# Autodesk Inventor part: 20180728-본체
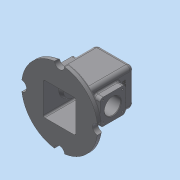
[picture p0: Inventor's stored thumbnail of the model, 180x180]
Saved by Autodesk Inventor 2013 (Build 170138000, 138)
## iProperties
Created: 2018-07
Part Number: 20180728-본체
Material: 일반
Document SubType Name: Modeling
Designer: dgall
Density: 1 g/cm^3
Author: dgall
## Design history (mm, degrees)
sketch "스케치1"
  geometry: A1 r 10 centre (0, -75) between (9.978, -74.333) and (-9.978, -74.333); A2 r 10 centre (-75, 0) between (-74.333, -9.978) and (-74.333, 9.978); A3 r 10 centre (0, 75) between (-9.978, 74.333) and (9.978, 74.333); A4 r 10 centre (75, 0) between (74.333, 9.978) and (74.333, -9.978); A5 r 75 centre (0, 0) between (-74.333, -9.978) and (-9.978, -74.333); A6 r 75 centre (0, 0) between (-9.978, 74.333) and (-74.333, 9.978); A7 r 75 centre (0, 0) between (9.978, -74.333) and (74.333, -9.978); A8 r 75 centre (0, 0) between (74.333, 9.978) and (9.978, 74.333); 1 further point
  constraints: 16 point on circle, 8 centre point, 6 equal radius, 2 horizontal alignment, 2 vertical alignment, 1 coincident
  dimensions: "d2" = 20 diameter of A1; "d3" = 75 radius of A7; "d4" = 75 distance of point (0, 0) A1.centre; "d5" = 150 distance of A2.centre A4.centre; "d6" = 75 distance of point (0, 0) A4.centre; "d7" = 75 distance of A3.centre point (0, 0)
extrude "돌출1" new body sketch "스케치1" distance "d8" = 10; taper "d9" = 0 deg
sketch "스케치2"
  geometry: L1 (-9.978, 0)-(-74.333, 0) reference; L2 (-9.978, 0)-(-9.978, -10) reference; L3 (-74.333, -10)-(-9.978, -10) reference; L4 (-74.333, 0)-(-74.333, -10) reference; L5 (9.978, 0)-(-9.978, 0) reference; L6 (9.978, 0)-(9.978, -10) reference; L7 (-9.978, -10)-(9.978, -10) reference; L8 (-9.978, 0)-(-9.978, -10) reference; L9 (74.333, 0)-(9.978, 0) reference; L10 (74.333, 0)-(74.333, -10) reference; L11 (9.978, -10)-(74.333, -10) reference; L12 (9.978, 0)-(9.978, -10) reference; L13 (-37, 0)-(-37, 100); L14 (-37, 100)-(37, 100); L15 (37, 100)-(37, 0); L16 (32, -10)-(32, 95); L17 (32, 95)-(-32, 95); L18 (-32, 95)-(-32, -10); L19 (-32, -10)-(32, -10); L20 (-37, 0)-(37, 0); 4 further points
  constraints: 16 end point, 4 midpoint, 4 perpendicular, 2 parallel, 2 point on line, 1 collinear, 1 vertical alignment
  dimensions: "d10" = 74 distance of L13.end L14.end; "d12" = 110 distance between parallel lines of L11 L14; "d13" = 5 distance between parallel lines of L14 L17; "d14" = 5 distance between parallel lines of L15 L16; "d15" = 5 distance between parallel lines of L13 L18
  node "투영된 루프1"
  node "투영된 루프2"
  node "투영된 루프3"
extrude "돌출2" join sketch "스케치2" stored distance "d16" = 74; taper "d17" = 0 deg
extrude "돌출3" cut sketch "스케치2" stored distance "d18" = 64; taper "d19" = 0 deg
sketch "스케치3"
  geometry: L1 (17, 57)-(57, 57); L2 (57, 57)-(57, 17); L3 (57, 17)-(17, 17); L4 (17, 17)-(17, 57); L5 (19.5, 54.5)-(54.5, 54.5); L6 (54.5, 54.5)-(54.5, 19.5); L7 (54.5, 19.5)-(19.5, 19.5); L8 (19.5, 19.5)-(19.5, 54.5); 5 further points
  constraints: 16 end point, 4 midpoint, 4 parallel, 4 perpendicular, 2 horizontal, 2 horizontal alignment, 2 vertical alignment
  dimensions: "d20" = 40 distance of L1.start L1.end; "d22" = 35 distance of L5.start L5.end
extrude "돌출4" join sketch "스케치3" distance "d23" = 7; taper "d24" = 0 deg
extrude "돌출5" join sketch "스케치3" distance "d25" = 10; taper "d26" = 0 deg
hole "구멍1" diameter "d29" = 21; stored, may be unused: countersink angle "d33" = 90 deg, drill point angle "d35" = 118 deg; dims "d27" = 17.5, "d28" = 17.5, "d30" = 6, "d31" = 28, "d32" = 4, "d34" = 8
sketch "스케치5"
  geometry: L1 (-74, 100)-(0, 100) reference; L2 (-62, 70)-(-12, 70); L3 (-12, 70)-(-12, 20); L4 (-12, 20)-(-62, 20); L5 (-62, 20)-(-62, 70); L6 (-62, 45)-(-12, 45); L7 (-27.022, -10)-(37.333, -10) reference; 3 further points
  constraints: 10 end point, 4 midpoint, 2 parallel, 2 perpendicular, 1 horizontal, 1 vertical alignment
  dimensions: "d37" = 50 distance of L2.start L2.end; "d39" = 55 distance between parallel lines of L7 L6
extrude "돌출6" join sketch "스케치5" distance "d40" = 13; taper "d41" = 0 deg
sketch "스케치6"
  geometry: L1 (0, 105)-(-64, 105) reference; L2 (-106.333, 0)-(-41.978, 0) reference; C1 r 25 at (-32, 55); 2 further points
  constraints: 1 centre point, 1 midpoint, 1 vertical alignment
  dimensions: "d42" = 55 distance from line of L2 C1.centre; "d43" = 50 diameter of C1
extrude "돌출7" join sketch "스케치6" distance "d44" = 7; taper "d45" = -20 deg
hole "구멍2" diameter "d48" = 32; stored, may be unused: countersink angle "d52" = 90 deg, drill point angle "d54" = 118 deg; dims "d46" = 25, "d47" = 25, "d49" = 6, "d50" = 4, "d51" = 2, "d53" = 8
fillet "모깎기1" dims "d55" = 6
hole "구멍3" diameter "d58" = 3.242; stored, may be unused: countersink angle "d62" = 90 deg, drill point angle "d64" = 118 deg; dims "d56" = 10, "d57" = 10, "d59" = 8, "d60" = 4, "d61" = 2, "d63" = 10
hole "구멍4" diameter "d67" = 3.242; stored, may be unused: countersink angle "d71" = 90 deg, drill point angle "d73" = 118 deg; dims "d65" = 10, "d66" = 10, "d68" = 8, "d69" = 4, "d70" = 2, "d72" = 10
hole "구멍5" diameter "d76" = 3.242; stored, may be unused: countersink angle "d80" = 90 deg, drill point angle "d82" = 118 deg; dims "d74" = 10, "d75" = 10, "d77" = 8, "d78" = 4, "d79" = 2, "d81" = 10
hole "구멍6" diameter "d85" = 3.242; stored, may be unused: countersink angle "d89" = 90 deg, drill point angle "d91" = 118 deg; dims "d83" = 10, "d84" = 10, "d86" = 8, "d87" = 4, "d88" = 2, "d90" = 10
hole "구멍7" diameter "d94" = 3.242; stored, may be unused: countersink angle "d98" = 90 deg, drill point angle "d100" = 118 deg; dims "d92" = 10, "d93" = 10, "d95" = 8, "d96" = 4, "d97" = 2, "d99" = 10
hole "구멍8" diameter "d103" = 3.242; stored, may be unused: countersink angle "d107" = 90 deg, drill point angle "d109" = 118 deg; dims "d101" = 10, "d102" = 10, "d104" = 8, "d105" = 4, "d106" = 2, "d108" = 10
hole "구멍9" diameter "d112" = 3.242; stored, may be unused: countersink angle "d116" = 90 deg, drill point angle "d118" = 118 deg; dims "d110" = 10, "d111" = 10, "d113" = 8, "d114" = 4, "d115" = 2, "d117" = 10
hole "구멍10" diameter "d121" = 3.242; stored, may be unused: countersink angle "d125" = 90 deg, drill point angle "d127" = 118 deg; dims "d119" = 10, "d120" = 10, "d122" = 8, "d123" = 4, "d124" = 2, "d126" = 10
fillet "모깎기2" dims "d128" = 3
fillet "모깎기3" dims "d129" = 3
fillet "모깎기4" dims "d130" = 8
fillet "모깎기5" dims "d131" = 8
fillet "모깎기6" dims "d132" = 3
fillet "모깎기7" dims "d133" = 3
fillet "모깎기8" dims "d134" = 3
fillet "모깎기9" dims "d135" = 3
chamfer "모따기1" distance "d136" = 1; stored, may be unused: second distance "d137" = 2, angle "d138" = 45 deg
sketch "스케치7"
  geometry: L1 (66, -89)-(66, 0) reference; L2 (14.5, 18)-(43.5, 18) reference; 2 further points
  constraints: 1 other
  dimensions: "d139" = 37 distance from line of L1 point (29, -12); "d140" = 30 distance from line of L2 point (29, -12)
extrude "돌출8" join sketch "스케치7" distance "d141" = 0.5; taper "d142" = 0 deg
node "솔리드1"
mirror "대칭1"
